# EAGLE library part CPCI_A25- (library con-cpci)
Compact PCI A 25 Source: www.erni.com
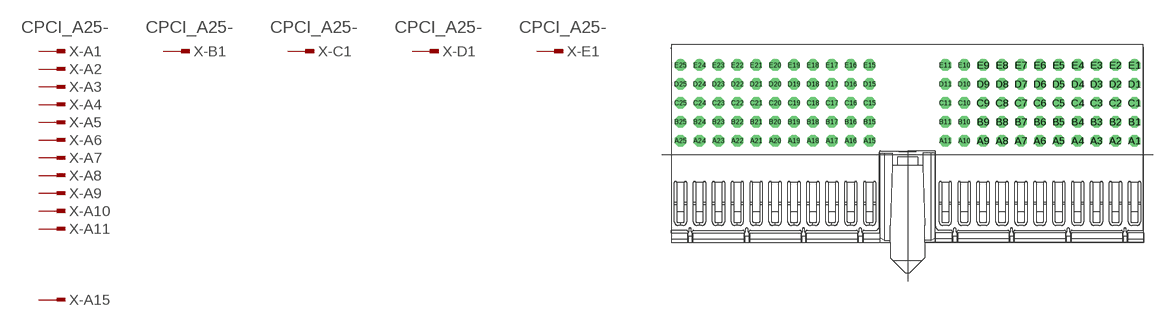
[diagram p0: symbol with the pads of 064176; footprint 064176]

Designator prefix X; gates -A1=PINV -B1=PINV -C1=PINV -D1=PINV -E1=PINV -A2=PIN -A3=PIN -A4=PIN -A5=PIN -A6=PIN -A7=PIN -A8=PIN -A9=PIN -A10=PIN -A11=PIN -A15=PIN -A16=PIN -A17=PIN -A18=PIN -A19=PIN -A20=PIN -A21=PIN -A22=PIN -A23=PIN -A24=PIN -A25=PIN -B2=PIN -B3=PIN -B4=PIN -B5=PIN -B6=PIN -B7=PIN -B8=PIN -B9=PIN -B10=PIN -B11=PIN -B15=PIN -B16=PIN -B17=PIN -B18=PIN -B19=PIN -B20=PIN -B21=PIN -B22=PIN -B23=PIN -B24=PIN -B25=PIN -C2=PIN -C3=PIN -C4=PIN -C5=PIN -C6=PIN -C7=PIN -C8=PIN -C9=PIN -C10=PIN -C11=PIN -C15=PIN -C16=PIN -C17=PIN -C18=PIN -C19=PIN -C20=PIN -C21=PIN -C22=PIN -C23=PIN -C24=PIN -C25=PIN -D2=PIN -D3=PIN -D4=PIN -D5=PIN -D6=PIN -D7=PIN -D8=PIN -D9=PIN -D10=PIN -D11=PIN -D15=PIN -D16=PIN -D17=PIN -D18=PIN -D19=PIN -D20=PIN -D21=PIN -D22=PIN -D23=PIN -D24=PIN -D25=PIN -E2=PIN -E3=PIN -E4=PIN -E5=PIN -E6=PIN -E7=PIN -E8=PIN -E9=PIN -E10=PIN -E11=PIN -E15=PIN -E16=PIN -E17=PIN -E18=PIN -E19=PIN -E20=PIN -E21=PIN -E22=PIN -E23=PIN -E24=PIN -E25=PIN

## CPCI_A25-064176  [064176]
A1  -A1:1  in
A2  -A2:1  in
A3  -A3:1  in
A4  -A4:1  in
A5  -A5:1  in
A6  -A6:1  in
A7  -A7:1  in
A8  -A8:1  in
A9  -A9:1  in
A10  -A10:1  in
A11  -A11:1  in
A15  -A15:1  in
A16  -A16:1  in
A17  -A17:1  in
A18  -A18:1  in
A19  -A19:1  in
A20  -A20:1  in
A21  -A21:1  in
A22  -A22:1  in
A23  -A23:1  in
A24  -A24:1  in
A25  -A25:1  in
B1  -B1:1  in
B2  -B2:1  in
B3  -B3:1  in
B4  -B4:1  in
B5  -B5:1  in
B6  -B6:1  in
B7  -B7:1  in
B8  -B8:1  in
B9  -B9:1  in
B10  -B10:1  in
B11  -B11:1  in
B15  -B15:1  in
B16  -B16:1  in
B17  -B17:1  in
B18  -B18:1  in
B19  -B19:1  in
B20  -B20:1  in
B21  -B21:1  in
B22  -B22:1  in
B23  -B23:1  in
B24  -B24:1  in
B25  -B25:1  in
C1  -C1:1  in
C2  -C2:1  in
C3  -C3:1  in
C4  -C4:1  in
C5  -C5:1  in
C6  -C6:1  in
C7  -C7:1  in
C8  -C8:1  in
C9  -C9:1  in
C10  -C10:1  in
C11  -C11:1  in
C15  -C15:1  in
C16  -C16:1  in
C17  -C17:1  in
C18  -C18:1  in
C19  -C19:1  in
C20  -C20:1  in
C21  -C21:1  in
C22  -C22:1  in
C23  -C23:1  in
C24  -C24:1  in
C25  -C25:1  in
D1  -D1:1  in
D2  -D2:1  in
D3  -D3:1  in
D4  -D4:1  in
D5  -D5:1  in
D6  -D6:1  in
D7  -D7:1  in
D8  -D8:1  in
D9  -D9:1  in
D10  -D10:1  in
D11  -D11:1  in
D15  -D15:1  in
D16  -D16:1  in
D17  -D17:1  in
D18  -D18:1  in
D19  -D19:1  in
D20  -D20:1  in
D21  -D21:1  in
D22  -D22:1  in
D23  -D23:1  in
D24  -D24:1  in
D25  -D25:1  in
E1  -E1:1  in
E2  -E2:1  in
E3  -E3:1  in
E4  -E4:1  in
E5  -E5:1  in
E6  -E6:1  in
E7  -E7:1  in
E8  -E8:1  in
E9  -E9:1  in
E10  -E10:1  in
E11  -E11:1  in
E15  -E15:1  in
E16  -E16:1  in
E17  -E17:1  in
E18  -E18:1  in
E19  -E19:1  in
E20  -E20:1  in
E21  -E21:1  in
E22  -E22:1  in
E23  -E23:1  in
E24  -E24:1  in
E25  -E25:1  in

## Footprint 064176 (pad centres in mm)
ERmet Federleiste A / ERmet Female Type A ohne Fixierstift / without locating pegs Abschirmblech oben montiert / shielding mounted on top Source: http://www.erni.com/DB/PDF-Drawing/ERmet/064176.pdf
drill 0.7 pad 1.016 octagon: A1 24,1.5; A2 22,1.5; A3 20,1.5; A4 18,1.5; A5 16,1.5; A6 14,1.5; A7 12,1.5; A8 10,1.5; A9 8,1.5; A10 6,1.5; A11 4,1.5; A15 -4,1.5; A16 -6,1.5; A17 -8,1.5; A18 -10,1.5; A19 -12,1.5; A20 -14,1.5; A21 -16,1.5; A22 -18,1.5; A23 -20,1.5; A24 -22,1.5; A25 -24,1.5; B1 24,3.5; B2 22,3.5; B3 20,3.5; B4 18,3.5; B5 16,3.5; B6 14,3.5; B7 12,3.5; B8 10,3.5; B9 8,3.5; B10 6,3.5; B11 4,3.5; B15 -4,3.5; B16 -6,3.5; B17 -8,3.5; B18 -10,3.5; B19 -12,3.5; B20 -14,3.5; B21 -16,3.5; B22 -18,3.5; B23 -20,3.5; B24 -22,3.5; B25 -24,3.5; C1 24,5.5; C2 22,5.5; C3 20,5.5; C4 18,5.5; C5 16,5.5; C6 14,5.5; C7 12,5.5; C8 10,5.5; C9 8,5.5; C10 6,5.5; C11 4,5.5; C15 -4,5.5; C16 -6,5.5; C17 -8,5.5; C18 -10,5.5; C19 -12,5.5; C20 -14,5.5; C21 -16,5.5; C22 -18,5.5; C23 -20,5.5; C24 -22,5.5; C25 -24,5.5; D1 24,7.5; D2 22,7.5; D3 20,7.5; D4 18,7.5; D5 16,7.5; D6 14,7.5; D7 12,7.5; D8 10,7.5; D9 8,7.5; D10 6,7.5; D11 4,7.5; D15 -4,7.5; D16 -6,7.5; D17 -8,7.5; D18 -10,7.5; D19 -12,7.5; D20 -14,7.5; D21 -16,7.5; D22 -18,7.5; D23 -20,7.5; D24 -22,7.5; D25 -24,7.5; E1 24,9.5; E2 22,9.5; E3 20,9.5; E4 18,9.5; E5 16,9.5; E6 14,9.5; E7 12,9.5; E8 10,9.5; E9 8,9.5; E10 6,9.5; E11 4,9.5; E15 -4,9.5; E16 -6,9.5; E17 -8,9.5; E18 -10,9.5; E19 -12,9.5; E20 -14,9.5; E21 -16,9.5; E22 -18,9.5; E23 -20,9.5; E24 -22,9.5; E25 -24,9.5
